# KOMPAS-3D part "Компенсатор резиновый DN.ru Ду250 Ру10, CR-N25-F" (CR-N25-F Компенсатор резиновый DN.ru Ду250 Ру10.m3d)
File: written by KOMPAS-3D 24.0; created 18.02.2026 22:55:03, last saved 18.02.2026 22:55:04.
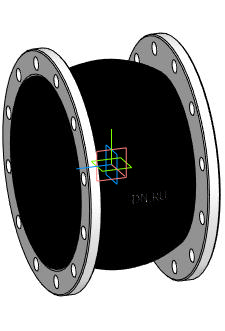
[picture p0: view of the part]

Document properties: Автор: DN.RU; Полное имя файла: D:\PROJECT CAD\DN.RU\...178(1)(ACTUALE). CR-N25-F Компенсатор резиновый DN.ru Ру10-16\DN250_PN10\CR-N25-F Компенсатор резиновый DN.ru Ду250 Ру10.m3d

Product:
- Body: Твердое тело2  | qty 1
    Масса: 66.860498
- Part/product: Компенсатор резиновый DN.ru Ду250 Ру10  | designation CR-N25-F
    Масса: 25
    Раздел спецификации: Прочие изделия
    Комментарий: D140-02398
    Примечание: D140-02398
    additional columns: Типовые

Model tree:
1. Твердое тело2  (labels: Твердое тело2)

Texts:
  CR-N25-F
